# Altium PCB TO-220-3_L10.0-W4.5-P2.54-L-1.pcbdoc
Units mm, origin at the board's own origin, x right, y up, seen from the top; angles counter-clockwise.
Board outline 22.73 x 17.23 mm, 2 copper layers (Top Layer, Bottom Layer), stack 0.07 mm thick; 1 components, 0 nets, 3 pads, 0 vias.
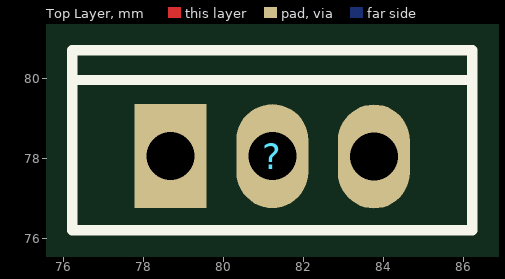
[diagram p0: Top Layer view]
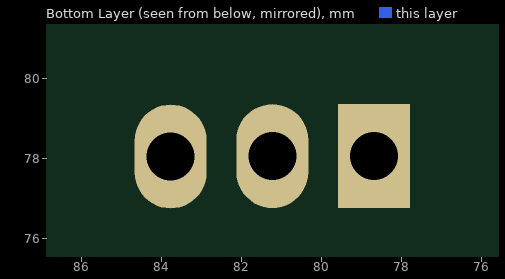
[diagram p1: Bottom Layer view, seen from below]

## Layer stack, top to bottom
Top Solder Mask Layer: solder mask 0.01, Dk 3.3
Top Layer: signal copper 0.035
Bottom Layer: signal copper 0.035
Bottom Solder Mask Layer: solder mask 0.01, Dk 3.3

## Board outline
92.58,69.85 69.85,69.85 69.85,87.085 92.58,87.085

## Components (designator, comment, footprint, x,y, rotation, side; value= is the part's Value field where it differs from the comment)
? "TO-220-3_L10.0-W4.5-P2.54-L-1" TO-220-3_L10.0-W4.5-P2.54-L-1 81.23,78.05 r0 top

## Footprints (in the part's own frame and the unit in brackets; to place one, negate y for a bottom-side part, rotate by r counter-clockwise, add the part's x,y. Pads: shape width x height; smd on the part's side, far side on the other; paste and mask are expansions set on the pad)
TO-220-3_L10.0-W4.5-P2.54-L-1 [mm]
  rect 1.8x2.6 hole 1.2 paste+0 mask+0.051: 1(-2.54,0.005)
  oval 1.8x2.6 hole 1.2 paste+0 mask+0.051: 2(0,0.005)
  oval 1.8x2.6 hole 1.2 copper offset 0,0 paste+0 mask+0.051: 3(2.54,-0.005)
  silkscreen extent -5,-1.85 5,2.65

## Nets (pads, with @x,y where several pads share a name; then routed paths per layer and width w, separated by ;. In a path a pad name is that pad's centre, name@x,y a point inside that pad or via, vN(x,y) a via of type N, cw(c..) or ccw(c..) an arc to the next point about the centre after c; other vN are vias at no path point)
pads on no net: ?.1 ?.2 ?.3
